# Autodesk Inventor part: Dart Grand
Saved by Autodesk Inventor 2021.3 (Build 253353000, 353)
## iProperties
Created: 2022-09
Part Number: Dart Grand
Material: Generic
Document SubType Name: Modeling
Designer: Administrator
Density: 1 g/cm^3
Appearance: Default
Title: Dart Grand
Author: Administrator
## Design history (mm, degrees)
feature "Glass-Dart Grand"
body "Solid1"
